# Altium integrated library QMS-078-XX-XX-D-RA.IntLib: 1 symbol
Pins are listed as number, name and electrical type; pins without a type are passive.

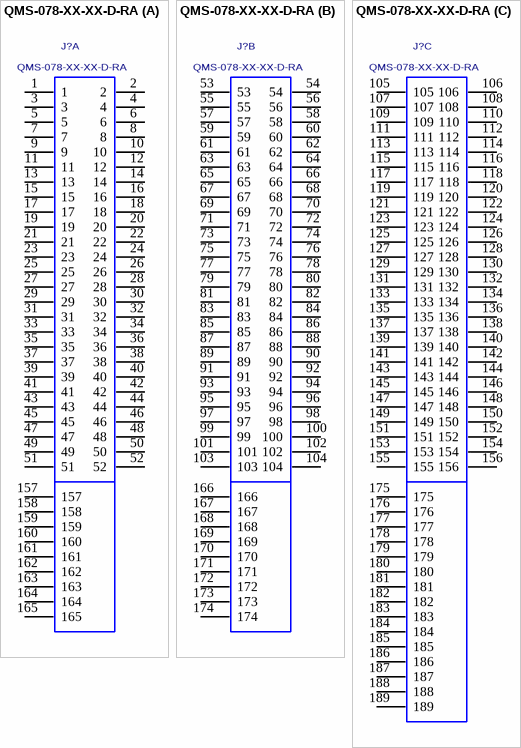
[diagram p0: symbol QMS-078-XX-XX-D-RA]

## QMS-078-XX-XX-D-RA
designator J?
0.635MM DUAL ROW RIGHT ANGLE SOCKET ASSEMBLY; MANUFACTURER: SAMTEC
footprint QMS-078-XX-XX-D-RA
part A pins: 1, 2, 3, 4, 5, 6, 7, 8, 9, 10, 11, 12, 13, 14, 15, 16, 17, 18, 19, 20, 21, 22, 23, 24, 25, 26, 27, 28, 29, 30, 31, 32, 33, 34, 35, 36, 37, 38, 39, 40, 41, 42, 43, 44, 45, 46, 47, 48, 49, 50, 51, 52, 157, 158, 159, 160, 161, 162, 163, 164, 165
part B pins: 53, 54, 55, 56, 57, 58, 59, 60, 61, 62, 63, 64, 65, 66, 67, 68, 69, 70, 71, 72, 73, 74, 75, 76, 77, 78, 79, 80, 81, 82, 83, 84, 85, 86, 87, 88, 89, 90, 91, 92, 93, 94, 95, 96, 97, 98, 99, 100, 101, 102, 103, 104, 166, 167, 168, 169, 170, 171, 172, 173, 174
part C pins: 105, 106, 107, 108, 109, 110, 111, 112, 113, 114, 115, 116, 117, 118, 119, 120, 121, 122, 123, 124, 125, 126, 127, 128, 129, 130, 131, 132, 133, 134, 135, 136, 137, 138, 139, 140, 141, 142, 143, 144, 145, 146, 147, 148, 149, 150, 151, 152, 153, 154, 155, 156, 175, 176, 177, 178, 179, 180, 181, 182, 183, 184, 185, 186, 187, 188, 189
